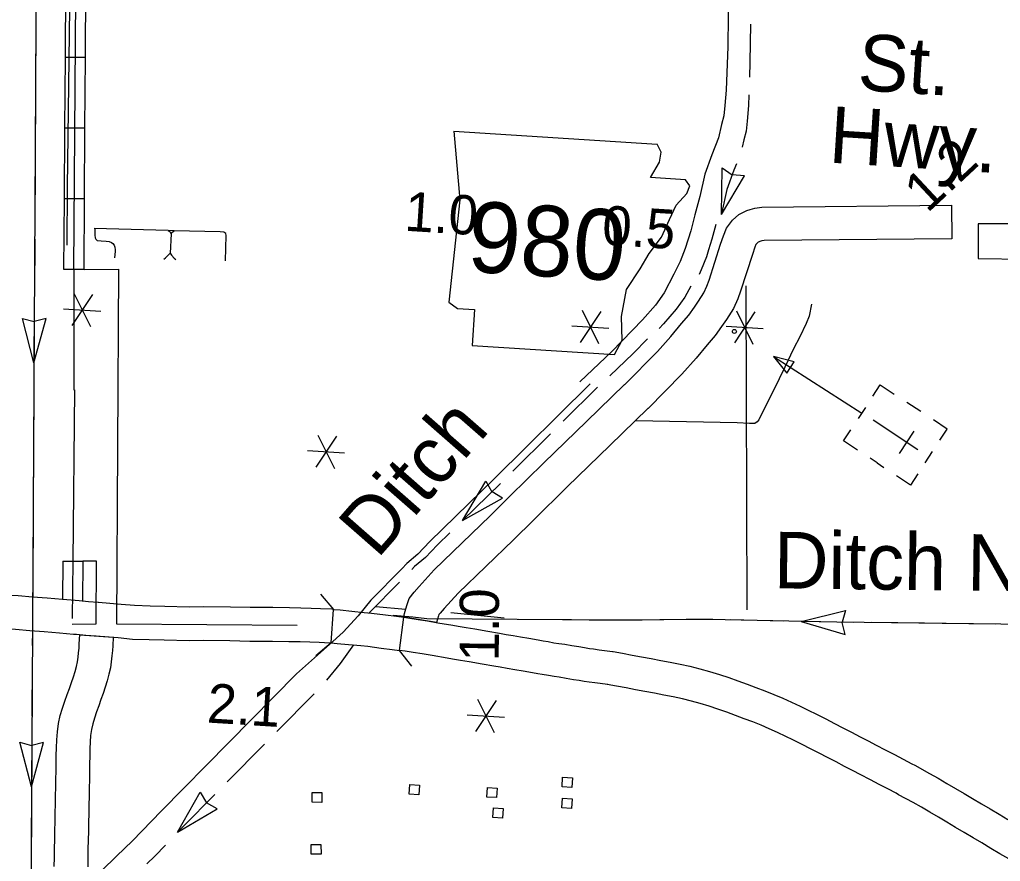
# Model space of a CAD drawing. Extents: x 1366406 to 1373462, y 376856 to 381998.
# Drawn here: x 1369434.3 to 1369553, y 379911.4 to 380013.3 of the extents above; entities that cross this region are included whole.
import ezdxf

# ---------------------------------------------------------------- set-up
doc = ezdxf.new("R2010")
doc.units = 0
for name, color, linetype in [('10', 7, 'Continuous'), ('21', 7, 'Continuous'), ('32', 7, 'Continuous'), ('33', 7, 'Continuous'), ('34', 7, 'Continuous'), ('37', 7, 'Continuous'), ('41', 7, 'Continuous'), ('43', 7, 'Continuous'), ('48', 7, 'Continuous'), ('5', 7, 'Continuous'), ('56', 7, 'Continuous'), ('57', 7, 'Continuous'), ('6', 7, 'Continuous')]:
    doc.layers.add(name, color=color, linetype=linetype)

msp = doc.modelspace()

# ---------------------------------------------------------------- linework, layer by layer
at = {"layer": '10'}
for p, q in [((1369507.5, 379969.06), (1369507.51, 379969.07)), ((1369510.37, 379966.2), (1369510.34, 379966.17)), ((1369506.04, 379936.76), (1369506.13, 379936.75))]:
    msp.add_line(p, q, dxfattribs=at)
for points in [[(1369507.5, 379969.06), (1369511.52, 379973.1), (1369513.13, 379974.9), (1369514.42, 379976.47), (1369515.29, 379977.49), (1369515.97, 379978.45), (1369516.48, 379979.17), (1369517.11, 379980.19), (1369517.48, 379981), (1369517.74, 379981.7), (1369519.14, 379986.08), (1369519.48, 379987.1), (1369519.84, 379988.01), (1369520.21, 379988.51), (1369520.59, 379988.97), (1369521.36, 379989.65), (1369522.31, 379990.15), (1369522.74, 379990.28), (1369523.29, 379990.44), (1369524.15, 379990.55), (1369547.08, 379990.78), (1369547.12, 379986.73)], [(1369547.12, 379986.73), (1369524.43, 379986.51), (1369524.15, 379986.47), (1369523.89, 379986.39), (1369523.82, 379986.37), (1369523.69, 379986.3), (1369523.5, 379986.13), (1369523.41, 379986.02), (1369523.28, 379985.71), (1369522.99, 379984.83), (1369521.57, 379980.37), (1369521.22, 379979.44), (1369520.7, 379978.29), (1369519.87, 379976.94), (1369519.27, 379976.1), (1369518.48, 379975), (1369517.53, 379973.87), (1369516.2, 379972.26), (1369514.46, 379970.32), (1369510.37, 379966.2)], [(1369484.77, 379940.28), (1369480.78, 379940.9), (1369480.87, 379941.38), (1369481.14, 379942.34), (1369481.46, 379943.18), (1369482.03, 379943.96), (1369482.64, 379944.65), (1369484.46, 379946.64), (1369491.26, 379953.17), (1369493.64, 379955.55), (1369497.74, 379959.59), (1369502.92, 379964.59), (1369507.51, 379969.07)], [(1369510.34, 379966.17), (1369505.74, 379961.69), (1369500.57, 379956.69), (1369496.49, 379952.67), (1369494.09, 379950.27), (1369487.36, 379943.81), (1369485.66, 379941.95), (1369485.19, 379941.42), (1369485.05, 379941.23), (1369484.99, 379941.07), (1369484.77, 379940.28)], [(1369443.79, 379942.71), (1369442.61, 379942.78), (1369441.49, 379942.88), (1369440.51, 379942.96), (1369439.47, 379943.05), (1369437.6, 379943.22), (1369435.86, 379943.34), (1369434.1, 379943.49), (1369432.36, 379943.6), (1369430.77, 379943.65), (1369430.64, 379939.6), (1369433.8, 379939.45), (1369435.54, 379939.3), (1369437.27, 379939.18), (1369439.1, 379939.01)], [(1369471.98, 379937.81), (1369472.29, 379941.85), (1369472.07, 379941.87), (1369470.71, 379941.93), (1369469.56, 379941.97), (1369468.32, 379942.02), (1369466.94, 379942.03), (1369464.93, 379942.07), (1369462.19, 379942.08), (1369459.81, 379942.12), (1369456.53, 379942.17), (1369454.81, 379942.14), (1369451.87, 379942.22), (1369450.08, 379942.25), (1369448.2, 379942.32), (1369446.57, 379942.47), (1369443.83, 379942.7)], [(1369472.29, 379941.85), (1369473.07, 379941.79), (1369474.5, 379941.65), (1369475.98, 379941.5), (1369476.9, 379941.41), (1369478.56, 379941.19), (1369479.92, 379941.03), (1369480.78, 379940.9)], [(1369505.51, 379932.75), (1369503.9, 379932.96), (1369503.22, 379933.05), (1369502.64, 379933.13), (1369502.02, 379933.24), (1369501.32, 379933.35), (1369500.45, 379933.5), (1369499.61, 379933.64), (1369498.99, 379933.74), (1369498.29, 379933.84), (1369497.56, 379933.98), (1369497.01, 379934.07), (1369496.39, 379934.17), (1369495.25, 379934.37), (1369494.22, 379934.54), (1369493.32, 379934.7), (1369492.47, 379934.85), (1369491.71, 379934.98), (1369490.27, 379935.23), (1369488.71, 379935.5), (1369487.65, 379935.69), (1369486.69, 379935.84), (1369486.03, 379935.97), (1369484.24, 379936.26), (1369483, 379936.48), (1369481.92, 379936.65), (1369480.95, 379936.79), (1369480.28, 379936.88), (1369480.78, 379940.9)], [(1369480.78, 379940.9), (1369481.52, 379940.8), (1369482.52, 379940.65), (1369483.66, 379940.48), (1369484.92, 379940.25), (1369486.72, 379939.96), (1369487.38, 379939.84), (1369488.33, 379939.68), (1369489.4, 379939.49), (1369490.96, 379939.22), (1369492.39, 379938.97), (1369493.17, 379938.84), (1369494.05, 379938.68), (1369494.91, 379938.53), (1369495.92, 379938.36), (1369497.06, 379938.16), (1369497.66, 379938.07), (1369498.27, 379937.97), (1369498.95, 379937.83), (1369499.58, 379937.75), (1369500.28, 379937.64), (1369501.13, 379937.49), (1369501.98, 379937.35), (1369502.68, 379937.23), (1369503.26, 379937.13), (1369503.76, 379937.07), (1369504.43, 379936.98), (1369506.04, 379936.76)], [(1369438.48, 379910.75), (1369438.49, 379911.84), (1369438.51, 379912.93), (1369438.54, 379914.01), (1369438.56, 379915.08), (1369438.58, 379916.15), (1369438.6, 379917.22), (1369438.62, 379918.27), (1369438.64, 379919.3), (1369438.66, 379920.32), (1369438.68, 379921.31), (1369438.69, 379922.27), (1369438.71, 379923.22), (1369438.72, 379924.16), (1369438.74, 379925.11), (1369438.78, 379926.06), (1369438.86, 379927.04), (1369439, 379928.03), (1369439.21, 379929), (1369439.48, 379929.92), (1369439.76, 379930.77), (1369440.05, 379931.56), (1369440.31, 379932.3), (1369440.57, 379933.03), (1369440.8, 379933.7), (1369441, 379934.34), (1369441.16, 379934.95), (1369441.28, 379935.52), (1369441.37, 379936.07), (1369441.43, 379936.62), (1369441.48, 379937.17), (1369441.51, 379937.69), (1369441.56, 379938.79), (1369445.6, 379938.49)], [(1369439.1, 379939.01), (1369440.8, 379938.87), (1369441.15, 379938.85), (1369442.29, 379938.74), (1369443.54, 379938.66)], [(1369445.6, 379938.49), (1369445.55, 379937.46), (1369445.51, 379936.87), (1369445.46, 379936.23), (1369445.38, 379935.53), (1369445.27, 379934.78), (1369445.1, 379934.01), (1369444.89, 379933.23), (1369444.65, 379932.45), (1369444.39, 379931.69), (1369444.13, 379930.94), (1369443.86, 379930.19), (1369443.59, 379929.44), (1369443.35, 379928.71), (1369443.14, 379928.01), (1369442.99, 379927.31), (1369442.88, 379926.59), (1369442.82, 379925.81), (1369442.79, 379924.97), (1369442.77, 379924.09), (1369442.75, 379923.17), (1369442.74, 379922.22), (1369442.73, 379921.24), (1369442.71, 379920.24), (1369442.69, 379919.22), (1369442.67, 379918.19), (1369442.65, 379917.14), (1369442.63, 379916.08), (1369442.61, 379915), (1369442.59, 379913.92), (1369442.56, 379912.84), (1369442.54, 379911.77), (1369442.53, 379910.7)], [(1369443.49, 379938.67), (1369446.21, 379938.44), (1369447.94, 379938.27), (1369449.97, 379938.2), (1369451.78, 379938.17), (1369454.79, 379938.09), (1369456.53, 379938.12), (1369459.75, 379938.08), (1369462.15, 379938.03), (1369464.88, 379938.02), (1369466.89, 379937.98), (1369468.23, 379937.97), (1369469.4, 379937.93), (1369470.55, 379937.88), (1369471.82, 379937.83), (1369471.98, 379937.81)], [(1369471.98, 379937.81), (1369472.71, 379937.75), (1369474.1, 379937.62), (1369475.58, 379937.47), (1369476.44, 379937.39), (1369478.05, 379937.17), (1369479.39, 379937.01), (1369480.28, 379936.88)], [(1369506.13, 379936.75), (1369507.28, 379936.55), (1369508.44, 379936.33), (1369509.58, 379936.12), (1369510.74, 379935.91), (1369511.89, 379935.69), (1369513.05, 379935.47), (1369514.24, 379935.23), (1369515.43, 379934.97), (1369516.63, 379934.68), (1369517.82, 379934.36), (1369519, 379933.99), (1369520.13, 379933.61), (1369521.24, 379933.22), (1369522.34, 379932.82), (1369523.42, 379932.42), (1369524.51, 379932), (1369525.6, 379931.56), (1369526.68, 379931.1), (1369527.73, 379930.62), (1369528.77, 379930.13), (1369529.66, 379929.71), (1369530.83, 379929.12), (1369531.88, 379928.6), (1369532.92, 379928.06), (1369533.96, 379927.52), (1369535, 379926.98), (1369536.03, 379926.44), (1369537.07, 379925.9), (1369537.91, 379925.46), (1369539.14, 379924.82), (1369540.19, 379924.28), (1369541.25, 379923.73), (1369542.31, 379923.17), (1369542.64, 379922.99), (1369544.43, 379922.01), (1369545.49, 379921.41), (1369546.54, 379920.8), (1369547.58, 379920.19), (1369548.61, 379919.57), (1369549.65, 379918.96), (1369550.71, 379918.33), (1369551.78, 379917.7), (1369552.85, 379917.05), (1369553.93, 379916.41)], [(1369554.03, 379911.65), (1369552.94, 379912.28), (1369551.85, 379912.93), (1369550.77, 379913.58), (1369549.7, 379914.22), (1369548.64, 379914.85), (1369547.59, 379915.47), (1369546.54, 379916.09), (1369545.51, 379916.71), (1369544.49, 379917.31), (1369543.48, 379917.9), (1369542.46, 379918.47), (1369540.7, 379919.43), (1369540.4, 379919.6), (1369539.37, 379920.15), (1369538.33, 379920.68), (1369537.29, 379921.22), (1369536.04, 379921.86), (1369535.19, 379922.31), (1369534.16, 379922.85), (1369533.12, 379923.39), (1369532.09, 379923.93), (1369531.06, 379924.46), (1369530.04, 379924.99), (1369529.03, 379925.5), (1369527.88, 379926.07), (1369527.03, 379926.48), (1369526.03, 379926.95), (1369525.04, 379927.4), (1369524.04, 379927.83), (1369523.03, 379928.24), (1369522, 379928.63), (1369520.95, 379929.02), (1369519.88, 379929.4), (1369518.81, 379929.78), (1369517.75, 379930.14), (1369516.69, 379930.47), (1369515.62, 379930.76), (1369514.52, 379931.02), (1369513.41, 379931.27), (1369512.28, 379931.49), (1369511.14, 379931.71), (1369509.99, 379931.93), (1369508.84, 379932.14), (1369507.7, 379932.35), (1369506.56, 379932.56), (1369505.43, 379932.76)]]:
    msp.add_lwpolyline(points, dxfattribs=at)
at = {"layer": '21'}
for p, q in [((1369486.85, 379999.75), (1369487.57, 379991.46)), ((1369511.95, 379997.21), (1369511.45, 379998.19)), ((1369511.74, 379995.99), (1369511.95, 379997.21)), ((1369510.66, 379994.13), (1369511.74, 379995.99)), ((1369514.9, 379993.87), (1369510.66, 379994.13)), ((1369515.41, 379993.15), (1369514.9, 379993.87)), ((1369515.07, 379992.21), (1369515.41, 379993.15)), ((1369487.57, 379991.46), (1369486.24, 379979.05)), ((1369513.75, 379990.78), (1369515.07, 379992.21)), ((1369512.95, 379989.05), (1369513.75, 379990.78)), ((1369512, 379986.91), (1369512.95, 379989.05)), ((1369510.5, 379984.95), (1369512, 379986.91)), ((1369509.42, 379983.09), (1369510.5, 379984.95)), ((1369507.75, 379980.59), (1369509.42, 379983.09)), ((1369507.14, 379977.33), (1369507.75, 379980.59)), ((1369486.24, 379979.05), (1369487.29, 379978.3)), ((1369487.29, 379978.3), (1369489.34, 379978.17)), ((1369489.34, 379978.17), (1369489.07, 379973.79)), ((1369507.23, 379974.44), (1369507.14, 379977.33)), ((1369489.07, 379973.79), (1369506.3, 379972.71)), ((1369506.3, 379972.71), (1369507.23, 379974.44))]:
    msp.add_line(p, q, dxfattribs=at)
msp.add_lwpolyline([(1369486.85, 379999.75), (1369511.45, 379998.19)], dxfattribs=at)
at = {"layer": '32'}
for p, q in [((1369442.25, 380008.67), (1369439.82, 380008.69)), ((1369442.19, 380000.12), (1369439.76, 380000.13)), ((1369442.14, 379991.56), (1369439.71, 379991.58)), ((1369442.08, 379983.01), (1369439.65, 379983.03)), ((1369439.51, 379947.7), (1369441.94, 379947.68))]:
    msp.add_line(p, q, dxfattribs=at)
for points in [[(1369440.86, 379983.02), (1369441.17, 380027.05), (1369441.25, 380045.71), (1369441.2, 380053.42), (1369441.18, 380062.92), (1369441.28, 380064.63), (1369441.42, 380065.33), (1369441.56, 380066.09), (1369441.64, 380066.56), (1369441.72, 380067.16), (1369441.89, 380068.43), (1369441.81, 380068.95), (1369441.63, 380069.39), (1369441.2, 380069.82), (1369440.8, 380069.93), (1369439.02, 380069.97), (1369437.18, 380069.95), (1369419.08, 380070.61), (1369411.46, 380070.91), (1369406.38, 380071.21), (1369403.18, 380071.34), (1369398.26, 380071.64), (1369392.89, 380071.86)], [(1369439.82, 380008.69), (1369439.88, 380017.24)], [(1369442.25, 380008.67), (1369442.31, 380017.22)], [(1369439.76, 380000.13), (1369439.82, 380008.69)], [(1369442.19, 380000.12), (1369442.25, 380008.67)], [(1369439.71, 379991.58), (1369439.76, 380000.13)], [(1369442.14, 379991.56), (1369442.19, 380000.12)], [(1369439.65, 379983.03), (1369439.71, 379991.58)], [(1369442.08, 379983.01), (1369442.14, 379991.56)], [(1369439.51, 379947.7), (1369439.47, 379943.05)], [(1369440.73, 379947.69), (1369440.66, 379940.75)], [(1369441.94, 379947.68), (1369441.9, 379942.85)]]:
    msp.add_lwpolyline(points, dxfattribs=at)
at = {"layer": '33'}
for points in [[(1369440.47, 380044.63), (1369440.42, 380041.14), (1369440.37, 380018.41), (1369440.31, 380014.64), (1369440.05, 379992.98), (1369439.98, 379985.97)], [(1369459.19, 379984.05), (1369459.3, 379987.12), (1369459.24, 379987.35), (1369458.99, 379987.52), (1369458.57, 379987.58), (1369453, 379987.7), (1369452.26, 379987.74), (1369443.3, 379987.97)], [(1369443.38, 379987.97), (1369443.4, 379987.16), (1369443.44, 379986.85), (1369443.52, 379986.68), (1369443.67, 379986.54), (1369444.14, 379986.47), (1369444.76, 379986.46), (1369445.12, 379986.38), (1369445.39, 379986.28), (1369445.58, 379986.14), (1369445.71, 379985.94), (1369445.81, 379985.71), (1369445.84, 379985.4), (1369445.87, 379985.19), (1369445.78, 379984.44)], [(1369452.26, 379987.74), (1369452.4, 379987.65), (1369452.51, 379987.51), (1369452.61, 379987.31), (1369452.71, 379987.49), (1369452.89, 379987.63), (1369453, 379987.7)], [(1369452.61, 379987.31), (1369452.5, 379985)], [(1369451.76, 379984.27), (1369451.93, 379984.44), (1369452.23, 379984.72), (1369452.5, 379985), (1369452.66, 379984.73), (1369452.98, 379984.4), (1369453.21, 379984.22)], [(1369530.16, 379978.81), (1369529.87, 379977.36), (1369529.51, 379976.49), (1369528.72, 379974.87), (1369527.98, 379973.41), (1369526.9, 379971.2), (1369526.25, 379969.78), (1369524.52, 379966.36), (1369523.99, 379965.24), (1369523.78, 379964.81), (1369523.57, 379964.55), (1369523.29, 379964.38), (1369522.63, 379964.38), (1369521.14, 379964.43), (1369508.89, 379964.67)]]:
    msp.add_lwpolyline(points, dxfattribs=at)
at = {"layer": '34'}
for points in [[(1369440.86, 379983.02), (1369440.83, 379968.46), (1369440.91, 379968.49)], [(1369440.93, 379968.44), (1369440.73, 379947.69)]]:
    msp.add_lwpolyline(points, dxfattribs=at)
at = {"layer": '37'}
for points in [[(1369470.71, 379943.7), (1369472.29, 379941.85)], [(1369480.78, 379940.9), (1369480.78, 379940.9)], [(1369471.98, 379937.81), (1369470.13, 379936.23)], [(1369481.78, 379934.97), (1369480.28, 379936.88)]]:
    msp.add_lwpolyline(points, dxfattribs=at)
at = {"layer": '43'}
for p, q in [((1369519.24, 379989.67), (1369519.33, 379995.32)), ((1369519.33, 379995.32), (1369520.54, 379994.48)), ((1369519.24, 379989.67), (1369522.04, 379994.34)), ((1369522.04, 379994.34), (1369520.56, 379994.47)), ((1369436.02, 379971.71), (1369434.62, 379977.09)), ((1369434.62, 379977.09), (1369436.04, 379976.7)), ((1369436.02, 379971.71), (1369437.49, 379977.07)), ((1369437.49, 379977.07), (1369436.06, 379976.7)), ((1369487.89, 379952.63), (1369490.74, 379957.4)), ((1369490.74, 379957.4), (1369491.46, 379956.11)), ((1369492.75, 379955.34), (1369491.48, 379956.1)), ((1369487.89, 379952.63), (1369492.75, 379955.34)), ((1369528.88, 379940.4), (1369534.28, 379941.72)), ((1369534.28, 379941.72), (1369533.86, 379940.3)), ((1369528.88, 379940.4), (1369534.21, 379938.84)), ((1369534.21, 379938.84), (1369533.86, 379940.28)), ((1369435.72, 379920.39), (1369434.32, 379925.77)), ((1369434.32, 379925.77), (1369435.74, 379925.38)), ((1369435.72, 379920.39), (1369437.19, 379925.75)), ((1369437.19, 379925.75), (1369435.76, 379925.38)), ((1369453.41, 379914.89), (1369456.16, 379919.72)), ((1369456.16, 379919.72), (1369456.9, 379918.44)), ((1369458.2, 379917.7), (1369456.92, 379918.43)), ((1369453.41, 379914.89), (1369458.2, 379917.7))]:
    msp.add_line(p, q, dxfattribs=at)
for points in [[(1369437.12, 380068.91), (1369436.72, 380067.71), (1369436.53, 380066.84), (1369436.4, 380065.79), (1369436.22, 380062.69), (1369436.35, 380053.64), (1369436.36, 380040.16), (1369436.34, 380027.08), (1369435.67, 379910.63), (1369435.48, 379901.35)], [(1369520.22, 380028.22), (1369520.02, 380009.99), (1369519.82, 380004.74), (1369519.67, 380002.85), (1369519.54, 380001.62), (1369519.27, 380000.55), (1369518.87, 379998.94), (1369518.07, 379996.89), (1369517.23, 379994.57), (1369516.62, 379991.83), (1369516.04, 379989.64), (1369515.52, 379987.7), (1369514.86, 379985.54), (1369514.24, 379983.98), (1369513.5, 379982.44), (1369512.31, 379980.17), (1369511.26, 379978.7), (1369509.7, 379976.92), (1369505.96, 379973.08), (1369502.09, 379969.41)], [(1369436.26, 380012.34), (1369436.22, 380005.93)], [(1369522.75, 380012.72), (1369522.7, 380008.12), (1369522.63, 380006.31)], [(1369436.21, 380003.79), (1369436.17, 379997.37)], [(1369522.55, 380004.17), (1369522.51, 380002.87), (1369522.36, 380000.98), (1369522.22, 379999.76), (1369521.95, 379998.69), (1369521.74, 379997.83)], [(1369436.16, 379995.23), (1369436.12, 379988.82)], [(1369521.06, 379995.81), (1369520.75, 379995.02), (1369519.91, 379992.71), (1369519.31, 379989.97), (1369519.23, 379989.67)], [(1369518.56, 379988.47), (1369518.09, 379986.69), (1369517.69, 379985.38)], [(1369436.11, 379986.68), (1369436.07, 379980.27)], [(1369517.69, 379985.38), (1369517.43, 379984.53), (1369516.81, 379982.97), (1369516.53, 379982.39)], [(1369515.52, 379980.99), (1369514.83, 379979.68), (1369513.78, 379978.2), (1369512.22, 379976.42), (1369511.7, 379975.88)], [(1369436.06, 379978.13), (1369436.02, 379971.71)], [(1369510.3, 379974.6), (1369508.57, 379972.83), (1369505.72, 379970.12)], [(1369503.34, 379969.18), (1369491.79, 379957.7), (1369483.96, 379950.08), (1369482.51, 379948.56), (1369481.16, 379947.43), (1369480.56, 379946.77), (1369476.82, 379942.98), (1369475.27, 379941.1), (1369473.46, 379939.11), (1369471.78, 379937.61), (1369467.82, 379934.07), (1369451.41, 379917.45), (1369447.95, 379913.84), (1369446.02, 379912), (1369437.09, 379903.28), (1369435.5, 379901.87), (1369434.66, 379901.35), (1369434.19, 379900.9)], [(1369436.01, 379969.57), (1369435.99, 379966.37)], [(1369504.25, 379968.78), (1369500.08, 379964.64)], [(1369435.99, 379966.37), (1369435.97, 379963.16)], [(1369498.56, 379963.13), (1369494.01, 379958.6)], [(1369435.96, 379961.02), (1369435.92, 379954.6)], [(1369492.49, 379957.1), (1369487.89, 379952.63)], [(1369435.91, 379952.47), (1369435.87, 379946.05)], [(1369486.36, 379951.13), (1369484.87, 379949.68), (1369484.09, 379948.87)], [(1369484.09, 379948.87), (1369483.42, 379948.16), (1369482.07, 379947.04), (1369481.75, 379946.68)], [(1369480.26, 379945.15), (1369476.61, 379941.44)], [(1369435.86, 379943.91), (1369435.86, 379943.38)], [(1369481.01, 379941.86), (1369477.39, 379942.17)], [(1369566.3, 379939.93), (1369533.21, 379940.3), (1369517.74, 379940.65), (1369506.83, 379940.54), (1369499.99, 379940.59), (1369483.59, 379940.72), (1369481.89, 379940.9), (1369479.51, 379941.11)], [(1369492.93, 379940.8), (1369486.48, 379941.45)], [(1369501.08, 379940.58), (1369499.99, 379940.59), (1369494.67, 379940.63)], [(1369509.63, 379940.57), (1369506.83, 379940.54), (1369503.22, 379940.57)], [(1369514.98, 379940.63), (1369511.77, 379940.59)], [(1369518.19, 379940.64), (1369517.74, 379940.65), (1369514.98, 379940.63)], [(1369526.74, 379940.45), (1369520.33, 379940.6)], [(1369535.29, 379940.28), (1369533.21, 379940.3), (1369528.88, 379940.4)], [(1369435.83, 379939.28), (1369435.82, 379937.5)], [(1369543.84, 379940.18), (1369537.43, 379940.26)], [(1369552.4, 379940.09), (1369545.98, 379940.16)], [(1369474.69, 379937.56), (1369473.09, 379935.32), (1369471.43, 379933.3)], [(1369435.81, 379935.36), (1369435.77, 379928.94)], [(1369469.94, 379931.62), (1369465.43, 379927.06)], [(1369435.76, 379926.81), (1369435.72, 379920.39)], [(1369463.93, 379925.54), (1369459.42, 379920.97)], [(1369457.91, 379919.45), (1369454.09, 379915.59), (1369453.42, 379914.88)], [(1369435.71, 379918.25), (1369435.69, 379915.05)], [(1369435.69, 379915.05), (1369435.68, 379911.84)], [(1369451.94, 379913.33), (1369450.64, 379911.97), (1369449.68, 379911.06)]]:
    msp.add_lwpolyline(points, dxfattribs=at)
at = {"layer": '48'}
for p, q in [((1369443.1, 379979.99), (1369440.61, 379976.24)), ((1369440.85, 379980.13), (1369442.86, 379976.1)), ((1369439.61, 379978.25), (1369444.1, 379977.97)), ((1369504.63, 379977.93), (1369502.14, 379974.18)), ((1369502.38, 379978.07), (1369504.38, 379974.04)), ((1369523.3, 379977.87), (1369520.81, 379974.12)), ((1369521.06, 379978.01), (1369523.06, 379973.98)), ((1369501.14, 379976.19), (1369505.63, 379975.91)), ((1369519.81, 379976.13), (1369524.3, 379975.85)), ((1369470.39, 379962.96), (1369472.39, 379958.93)), ((1369472.63, 379962.82), (1369470.14, 379959.07)), ((1369469.14, 379961.09), (1369473.63, 379960.81)), ((1369491.97, 379930.84), (1369489.48, 379927.09)), ((1369489.72, 379930.98), (1369491.73, 379926.95)), ((1369488.48, 379929.11), (1369492.97, 379928.82))]:
    msp.add_line(p, q, dxfattribs=at)
at = {"layer": '5'}
msp.add_lwpolyline([(1369522.34, 379941.79), (1369522.22, 379981.04)], dxfattribs=at)
at = {"layer": '56'}
for points in [[(1369499.95, 379920.37), (1369500.02, 379921.54), (1369501.2, 379921.47), (1369501.12, 379920.3)], [(1369481.45, 379919.5), (1369481.52, 379920.67), (1369482.7, 379920.59), (1369482.62, 379919.42)], [(1369490.85, 379919.14), (1369490.93, 379920.31), (1369492.1, 379920.23), (1369492.02, 379919.07)], [(1369469.69, 379918.51), (1369469.7, 379919.69), (1369470.87, 379919.68), (1369470.86, 379918.5)], [(1369499.92, 379917.84), (1369499.99, 379919.01), (1369501.16, 379918.94), (1369501.09, 379917.77)], [(1369491.58, 379916.65), (1369491.66, 379917.82), (1369492.83, 379917.74), (1369492.75, 379916.57)], [(1369469.59, 379912.21), (1369469.57, 379913.38), (1369470.74, 379913.4), (1369470.77, 379912.23)]]:
    msp.add_lwpolyline(points, close=True, dxfattribs=at)
at = {"layer": '57'}
for p, q in [((1369543.37, 379965.81), (1369541.67, 379966.92)), ((1369536.69, 379966.31), (1369535.8, 379964.96)), ((1369543.02, 379961.19), (1369537.6, 379964.75)), ((1369540.31, 379962.97), (1369540.31, 379962.97)), ((1369540.31, 379962.97), (1369540.31, 379962.97)), ((1369542.55, 379963.44), (1369540.76, 379960.72)), ((1369543.92, 379959.62), (1369544.81, 379960.97)), ((1369538.08, 379959.59), (1369537.23, 379960.15)), ((1369538.08, 379959.59), (1369538.92, 379959.04))]:
    msp.add_line(p, q, dxfattribs=at)
for points in [[(1369556.08, 379988.54), (1369550.34, 379988.52), (1369550.32, 379984.35), (1369556, 379984.28)], [(1369525.53, 379972.49), (1369536.24, 379965.63)], [(1369537.58, 379967.67), (1369538.47, 379969.03), (1369540.16, 379967.91)], [(1369545.7, 379962.33), (1369546.59, 379963.69), (1369544.9, 379964.8)], [(1369535.71, 379961.15), (1369534.02, 379962.26), (1369534.91, 379963.61)], [(1369543.03, 379958.27), (1369542.14, 379956.92), (1369540.45, 379958.03)]]:
    msp.add_lwpolyline(points, dxfattribs=at)
msp.add_lwpolyline([(1369527.17, 379970.46), (1369528.06, 379971.85), (1369525.53, 379972.49)], close=True, dxfattribs=at)
msp.add_circle((1369520.81, 379975.51), 0.243, dxfattribs=at)
at = {"layer": '6'}
for points in [[(1369442.08, 379983.03), (1369446.26, 379983.06), (1369446.03, 379940.13)], [(1369443.56, 379940.1), (1369443.59, 379947.71), (1369441.94, 379947.7)], [(1369440.66, 379940.09), (1369443.56, 379940.1)], [(1369446.03, 379940.13), (1369467.88, 379939.97)]]:
    msp.add_lwpolyline(points, dxfattribs=at)

# ---------------------------------------------------------------- texts
at = {"layer": '21'}
msp.add_text('980', height=8.554, rotation=356.4139, dxfattribs=at).set_placement((1369488.34, 379982.78))
at = {"layer": '41'}
for s, p in [('St.', (1369535.63, 380004.75)), ('Hwy.', (1369532.15, 379995.96))]:
    msp.add_text(s, height=6.843, rotation=356.4139, dxfattribs=at).set_placement(p)
at = {"layer": '43'}
for s, height, rotation, p in [('Ditch', 6.843, 48.7873, (1369477.58, 379947.87)), ('Ditch No.  7A', 6.8429, 359.307, (1369525.56, 379944.42))]:
    msp.add_text(s, height=height, rotation=rotation, dxfattribs=at).set_placement(p)
at = {"layer": '48'}
for s, rotation, p in [('1.2', 43.0233, (1369544.16, 379989.76)), ('1.0', 356.4139, (1369480.8, 379987.71)), ('0.5', 356.4139, (1369504.7, 379986.03)), ('1.0', 89.8066, (1369492.29, 379935.56)), ('2.1', 356.4139, (1369456.89, 379928.17))]:
    msp.add_text(s, height=4.752, rotation=rotation, dxfattribs=at).set_placement(p)

doc.saveas('drawing.dxf')
